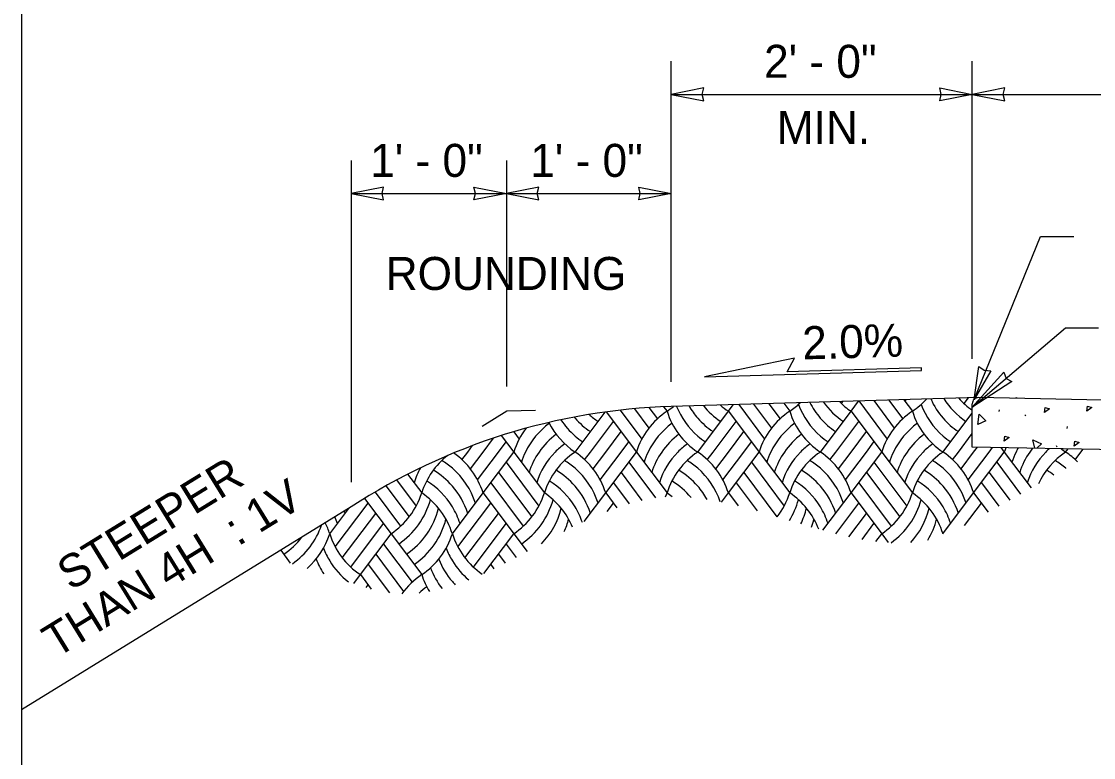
# Model space of a CAD drawing. Extents: x 99862 to 103151, y 100000 to 102076.
# Drawn here: x 99862 to 100381, y 101323 to 101680 of the extents above; entities that cross this region are included whole.
import ezdxf

# ---------------------------------------------------------------- set-up
doc = ezdxf.new("R2010")
doc.units = 0
for name, color, linetype in [('Level 1', 7, 'Continuous'), ('Level 13', 7, 'Continuous'), ('Level 15', 7, 'Continuous'), ('Level 20', 7, 'Continuous'), ('Level 28', 7, 'Continuous'), ('Level 34', 7, 'Continuous'), ('Level 4', 7, 'Continuous'), ('Level 6', 7, 'Continuous')]:
    doc.layers.add(name, color=color, linetype=linetype)

msp = doc.modelspace()

# ---------------------------------------------------------------- linework, layer by layer
at = {"layer": 'Level 1'}
msp.add_lwpolyline([(99862, 99999.5), (103151, 99999.5), (103151, 102075.5), (99862, 102075.5)], close=True, dxfattribs=at)
at = {"layer": 'Level 13'}
for p, q in [((100343.49, 101497.73), (100343.58, 101497.66)), ((100343.8, 101497.73), (100343.98, 101497.59)), ((100335.5, 101490.97), (100335.56, 101491.85)), ((100347.88, 101489.43), (100348.4, 101489.05)), ((100368.43, 101482.83), (100368.49, 101483.7)), ((100362.99, 101474.6), (100363.34, 101473.88))]:
    msp.add_line(p, q, dxfattribs=at)
for points in [[(100377.89, 101491.14), (100378.14, 101493.59), (100380.26, 101492.95), (100377.89, 101491.14)], [(100325.06, 101484.62), (100325.76, 101489.7), (100328.94, 101486.41), (100325.14, 101484.65)], [(100357.43, 101490.45), (100357.67, 101492.9), (100359.8, 101492.26), (100357.43, 101490.45)], [(100337.92, 101476.59), (100338.16, 101479.04), (100340.29, 101478.4), (100337.92, 101476.59)], [(100352.66, 101473.19), (100351.78, 101477.32), (100355.89, 101475.32), (100353.72, 101473.17)], [(100371.78, 101474.13), (100372.03, 101476.58), (100374.15, 101475.93), (100371.78, 101474.13)]]:
    msp.add_lwpolyline(points, dxfattribs=at)
at = {"layer": 'Level 15'}
for p, q in [((100176.64, 101516.59), (100176.64, 101660.67)), ((100322.4, 101516.59), (100322.4, 101660.67)), ((100176.64, 101644.67), (100322.4, 101644.67)), ((100322.4, 101644.67), (100753.65, 101644.67)), ((100021.66, 101612.67), (100021.66, 101456.76)), ((100096.8, 101612.67), (100096.8, 101503.09)), ((100021.66, 101596.67), (100096.8, 101596.67)), ((100096.8, 101596.67), (100176.64, 101596.67)), ((100176.64, 101505.43), (100176.64, 101596.67)), ((100323.3, 101496.87), (100355.53, 101575.76)), ((100355.53, 101575.76), (100371.53, 101575.76)), ((100322.2, 101492.93), (100367.51, 101531.52)), ((100367.51, 101531.52), (100383.51, 101531.52))]:
    msp.add_line(p, q, dxfattribs=at)
for points in [[(100176.64, 101644.67), (100192.37, 101641.59), (100191.64, 101644.67), (100192.37, 101647.76)], [(100322.4, 101644.67), (100306.68, 101641.59), (100307.4, 101644.67), (100306.68, 101647.76)], [(100322.4, 101644.67), (100338.13, 101641.59), (100337.4, 101644.67), (100338.13, 101647.76)], [(100021.66, 101596.67), (100037.39, 101593.59), (100036.66, 101596.67), (100037.39, 101599.76)], [(100096.8, 101596.67), (100081.07, 101593.59), (100081.8, 101596.67), (100081.07, 101599.76)], [(100096.8, 101596.67), (100112.52, 101593.59), (100111.8, 101596.67), (100112.52, 101599.76)], [(100176.64, 101596.67), (100160.92, 101593.59), (100161.64, 101596.67), (100160.92, 101599.76)], [(100322.2, 101492.93), (100337.64, 101510), (100338.77, 101507.04), (100341.51, 101505.46)], [(100323.3, 101496.87), (100325.52, 101512.74), (100328.2, 101511.05), (100331.35, 101510.73)]]:
    msp.add_lwpolyline(points, close=True, dxfattribs=at)
at = {"layer": 'Level 20'}
msp.add_lwpolyline([(100297.81, 101512.09), (100232.76, 101510.21), (100236.31, 101516.8), (100192.81, 101507.82), (100297.85, 101510.86)], close=True, dxfattribs=at)
at = {"layer": 'Level 28'}
for p, q in [((100325.46, 101497.73), (100176.64, 101493.43)), ((100097.02, 101491.13), (100085.1, 101483.8)), ((100111, 101491.53), (100097.02, 101491.13))]:
    msp.add_line(p, q, dxfattribs=at)
msp.add_arc((100185.68, 101193.57), 300, 91.7265, 123.1427, dxfattribs=at)
at = {"layer": 'Level 34'}
for p, q in [((100172.98, 101493.3), (100174.6, 101491.14)), ((100204.3, 101491.14), (100206.67, 101494.3)), ((100209.3, 101494.37), (100221.82, 101477.67)), ((100216.56, 101494.58), (100225.27, 101482.98)), ((100223.83, 101494.79), (100229.35, 101487.44)), ((100231.1, 101495), (100234, 101491.14)), ((100259.04, 101494.83), (100259.8, 101495.83)), ((100263.7, 101491.14), (100267.38, 101496.05)), ((100267.41, 101496.09), (100281.22, 101477.67)), ((100274.7, 101496.26), (100284.66, 101482.98)), ((100281.86, 101496.62), (100288.74, 101487.44)), ((100289.27, 101496.63), (100293.4, 101491.14)), ((100318.44, 101494.83), (100320.51, 101497.59)), ((100130.06, 101471.34), (100144.61, 101490.74)), ((100145.15, 101490.81), (100159.75, 101471.34)), ((100151.94, 101491.66), (100162.43, 101477.67)), ((100158.83, 101492.36), (100165.87, 101482.98)), ((100165.85, 101492.91), (100169.95, 101487.44)), ((100189.45, 101471.34), (100204.3, 101491.14)), ((100204.3, 101491.14), (100219.15, 101471.34)), ((100248.85, 101471.34), (100263.7, 101491.14)), ((100263.7, 101491.14), (100278.55, 101471.34)), ((100308.24, 101471.34), (100322.4, 101490.21)), ((100137.48, 101471.34), (100148.62, 101486.19)), ((100196.88, 101471.34), (100208.01, 101486.19)), ((100256.27, 101471.34), (100267.41, 101486.19)), ((100085.51, 101471.34), (100090.58, 101478.09)), ((100094.36, 101479.33), (100100.36, 101471.34)), ((100100.39, 101481.19), (100103.03, 101477.67)), ((100144.91, 101471.34), (100152.33, 101481.24)), ((100204.3, 101471.34), (100211.73, 101481.24)), ((100263.7, 101471.34), (100271.12, 101481.24)), ((100315.67, 101471.34), (100322.4, 101480.31)), ((100078.08, 101471.34), (100080.47, 101474.51)), ((100092.93, 101471.34), (100096.65, 101476.29)), ((100152.33, 101471.34), (100156.04, 101476.29)), ((100211.73, 101471.34), (100215.44, 101476.29)), ((100271.12, 101471.34), (100274.83, 101476.29)), ((100323.09, 101471.34), (100324.9, 101473.74)), ((100330.52, 101471.34), (100332.21, 101473.6)), ((100336.31, 101473.51), (100337.94, 101471.34)), ((100367.64, 101471.34), (100368.79, 101472.86)), ((100375.06, 101471.34), (100376.1, 101472.72)), ((100075.31, 101467.64), (100078.08, 101471.34)), ((100079.39, 101463.18), (100085.51, 101471.34)), ((100082.83, 101457.87), (100092.93, 101471.34)), ((100085.51, 101451.54), (100100.36, 101471.34)), ((100100.36, 101471.34), (100115.21, 101451.54)), ((100134.71, 101467.64), (100137.48, 101471.34)), ((100138.79, 101463.18), (100144.91, 101471.34)), ((100142.23, 101457.87), (100152.33, 101471.34)), ((100144.91, 101451.54), (100159.75, 101471.34)), ((100159.75, 101471.34), (100174.6, 101451.54)), ((100194.11, 101467.64), (100196.88, 101471.34)), ((100198.18, 101463.18), (100204.3, 101471.34)), ((100201.63, 101457.87), (100211.73, 101471.34)), ((100204.3, 101451.54), (100219.15, 101471.34)), ((100219.15, 101471.34), (100234, 101451.54)), ((100253.5, 101467.64), (100256.27, 101471.34)), ((100257.58, 101463.18), (100263.7, 101471.34)), ((100261.02, 101457.87), (100271.12, 101471.34)), ((100263.7, 101451.54), (100278.55, 101471.34)), ((100278.55, 101471.34), (100293.4, 101451.54)), ((100312.9, 101467.64), (100315.67, 101471.34)), ((100316.98, 101463.18), (100323.09, 101471.34)), ((100320.42, 101457.87), (100330.52, 101471.34)), ((100323.09, 101451.54), (100337.94, 101471.34)), ((100337.94, 101471.34), (100350.97, 101453.96)), ((100372.29, 101467.64), (100375.06, 101471.34)), ((100096.65, 101466.39), (100112.53, 101445.2)), ((100156.04, 101466.39), (100169.01, 101449.1)), ((100215.44, 101466.39), (100231.33, 101445.2)), ((100274.83, 101466.39), (100290.72, 101445.2)), ((100334.23, 101466.39), (100345.76, 101451.02)), ((100043.67, 101457.83), (100053.14, 101445.2)), ((100049, 101460.62), (100055.81, 101451.54)), ((100092.93, 101461.44), (100109.09, 101439.9)), ((100152.33, 101461.44), (100162.48, 101447.91)), ((100211.73, 101461.44), (100227.79, 101440.02)), ((100271.12, 101461.44), (100287.28, 101439.9)), ((100330.52, 101461.44), (100340.54, 101448.07)), ((100033.23, 101451.95), (100045.62, 101435.43)), ((100038.42, 101454.93), (100049.69, 101439.9)), ((100070.66, 101431.74), (100085.51, 101451.54)), ((100085.51, 101451.54), (100100.36, 101431.74)), ((100089.22, 101456.49), (100105.01, 101435.43)), ((100134.48, 101437.64), (100144.91, 101451.54)), ((100144.91, 101451.54), (100150.28, 101444.37)), ((100148.62, 101456.49), (100156.24, 101446.33)), ((100201, 101447.13), (100204.3, 101451.54)), ((100204.3, 101451.54), (100208.99, 101445.29)), ((100208.01, 101456.49), (100218.28, 101442.8)), ((100250.11, 101433.43), (100263.7, 101451.54)), ((100263.7, 101451.54), (100278.55, 101431.74)), ((100267.41, 101456.49), (100283.2, 101435.43)), ((100308.24, 101431.74), (100323.09, 101451.54)), ((100323.09, 101451.54), (100330.11, 101442.19)), ((100326.81, 101456.49), (100335.32, 101445.13)), ((100013.94, 101425.4), (100029.83, 101446.59)), ((100028.12, 101448.86), (100040.96, 101431.74)), ((100073.33, 101425.4), (100089.22, 101446.59)), ((100145.59, 101442.55), (100148.62, 101446.59)), ((100256.32, 101431.8), (100267.41, 101446.59)), ((100318.66, 101435.73), (100326.81, 101446.59)), ((100011.26, 101431.74), (100020.49, 101444.04)), ((100017.38, 101420.1), (100033.54, 101441.64)), ((100076.78, 101420.1), (100092.93, 101441.64)), ((100262.63, 101430.32), (100271.12, 101441.64)), ((100021.46, 101415.63), (100037.25, 101436.69)), ((100080.86, 101415.63), (100096.65, 101436.69)), ((100269.09, 101429.03), (100274.83, 101436.69)), ((100026.11, 101411.94), (100040.96, 101431.74)), ((100040.96, 101431.74), (100055.81, 101411.94)), ((100085.97, 101412.56), (100100.36, 101431.74)), ((100100.36, 101431.74), (100106.83, 101423.11)), ((100275.77, 101428.04), (100278.55, 101431.74)), ((100278.55, 101431.74), (100281.71, 101427.52)), ((100037.25, 101426.79), (100051.16, 101408.25)), ((100096.65, 101426.79), (100101.52, 101420.29)), ((99987.55, 101423.77), (99992.18, 101417.58)), ((100033.54, 101421.84), (100047.08, 101403.78)), ((100092.93, 101421.84), (100096.18, 101417.51)), ((100029.83, 101416.89), (100040.2, 101403.06)), ((100089.22, 101416.89), (100090.77, 101414.83)), ((100022.91, 101407.67), (100026.11, 101411.94)), ((100026.11, 101411.94), (100031.36, 101404.94)), ((100028.89, 101405.74), (100029.83, 101406.99))]:
    msp.add_line(p, q, dxfattribs=at)
for centre, start, end in [((100153.64, 101522.32), 303.9036, 309.8156), ((100214.13, 101507.47), 201.8244, 228.9599), ((100217.84, 101512.42), 209.9238, 220.9416), ((100221.55, 101517.37), 218.6985, 236.0964), ((100225.26, 101522.32), 228.6448, 236.0964), ((100213.04, 101522.32), 303.9036, 313.8709), ((100273.52, 101507.47), 200.2432, 228.9599), ((100277.23, 101512.42), 206.9922, 220.9416), ((100280.95, 101517.37), 215.4869, 236.0964), ((100284.66, 101522.32), 224.9354, 236.0964), ((100268.72, 101527.27), 303.9036, 305.3853), ((100272.44, 101522.32), 303.9036, 317.6315), ((100332.92, 101507.47), 200.2432, 228.9599), ((100336.63, 101512.42), 204.1301, 220.9416), ((100340.34, 101517.37), 212.3917, 236.0964), ((100344.05, 101522.32), 221.4398, 234.814), ((100158.44, 101512.42), 219.9686, 220.9416), ((100162.15, 101517.37), 227.7254, 236.0964), ((100195.56, 101459.95), 123.9036, 162.3566), ((100210.41, 101502.52), 197.6434, 236.0964), ((100254.96, 101459.95), 123.9036, 162.3566), ((100269.81, 101502.52), 197.6434, 236.0964), ((100314.36, 101459.95), 123.9036, 162.3566), ((100329.21, 101502.52), 197.6434, 236.0964), ((100136.17, 101459.95), 142.3389, 162.3566), ((100139.88, 101455), 126.3063, 154.2266), ((100151.02, 101502.52), 206.6043, 236.0964), ((100154.73, 101507.47), 213.0285, 228.9599), ((100158.44, 101512.42), 220.9415, 236.0964), ((100199.28, 101455), 126.3063, 154.2266), ((100217.84, 101512.42), 220.9415, 236.0964), ((100258.67, 101455), 126.3063, 154.2266), ((100277.23, 101512.42), 220.9415, 236.0964), ((100318.07, 101455), 126.3063, 154.2266), ((100336.63, 101512.42), 220.9415, 236.0964), ((100143.59, 101450.05), 127.1006, 145.4911), ((100154.73, 101507.47), 228.9599, 236.0964), ((100202.99, 101450.05), 127.1006, 145.4911), ((100214.12, 101507.47), 228.9599, 236.0964), ((100262.38, 101450.05), 127.1006, 145.4911), ((100273.52, 101507.47), 228.9599, 236.0964), ((100321.78, 101450.05), 127.1006, 145.4911), ((100332.92, 101507.47), 228.9599, 236.0964), ((100147.31, 101445.1), 126.331, 135.7128), ((100206.7, 101445.1), 126.331, 135.7128), ((100266.1, 101445.1), 126.331, 135.7128), ((100325.49, 101445.1), 126.331, 135.7128), ((100373.75, 101459.95), 158.9143, 162.3566), ((100377.46, 101455), 150.7709, 154.2266), ((100381.18, 101450.05), 141.9503, 145.4911), ((100384.89, 101445.1), 131.9516, 135.7128), ((100388.6, 101502.52), 231.9565, 236.0964), ((100091.62, 101440.15), 128.1669, 162.3566), ((100045.99, 101435.2), 48.9597, 58.5465), ((100049.7, 101440.15), 17.6434, 54.9273), ((100139.88, 101455), 154.2265, 162.3566), ((100143.59, 101450.05), 145.491, 162.3566), ((100147.31, 101445.1), 135.7127, 162.3566), ((100151.02, 101440.15), 123.9036, 162.3566), ((100105.38, 101435.2), 48.9597, 58.5465), ((100109.1, 101440.15), 17.6434, 56.0963), ((100199.28, 101455), 154.2265, 162.3566), ((100202.99, 101450.05), 145.491, 162.3566), ((100206.7, 101445.1), 135.7127, 162.3566), ((100210.41, 101440.15), 123.9036, 162.3566), ((100164.78, 101435.2), 48.9597, 58.5465), ((100168.49, 101440.15), 17.6434, 56.0963), ((100258.67, 101455), 154.2265, 162.3566), ((100262.38, 101450.05), 145.491, 162.3566), ((100266.1, 101445.1), 135.7127, 162.3566), ((100269.81, 101440.15), 123.9036, 162.3566), ((100224.18, 101435.2), 48.9597, 58.5465), ((100227.89, 101440.15), 17.6434, 56.0963), ((100318.07, 101455), 154.2265, 162.3566), ((100321.78, 101450.05), 145.491, 162.3566), ((100325.49, 101445.1), 135.7127, 162.3566), ((100329.21, 101440.15), 123.9036, 162.3566), ((100283.57, 101435.2), 48.9597, 58.5465), ((100287.28, 101440.15), 17.6434, 56.0963), ((100377.46, 101455), 154.2265, 162.3566), ((100381.18, 101450.05), 145.491, 162.3566), ((100384.89, 101445.1), 135.7127, 162.3566), ((100388.6, 101440.15), 123.9036, 155.1174), ((100342.97, 101435.2), 48.9597, 58.5465), ((100346.68, 101440.15), 44.7448, 56.0963), ((100087.91, 101445.1), 150.2466, 162.3566), ((100042.28, 101430.25), 40.9413, 59.3021), ((100045.99, 101435.2), 17.6434, 48.9597), ((100101.67, 101430.25), 40.9413, 59.3021), ((100105.38, 101435.2), 17.6434, 48.9597), ((100161.07, 101430.25), 40.9413, 59.3021), ((100164.78, 101435.2), 18.7051, 48.9597), ((100220.46, 101430.25), 40.9413, 59.3021), ((100224.18, 101435.2), 17.6434, 48.9597), ((100279.86, 101430.25), 40.9413, 59.3021), ((100283.57, 101435.2), 17.6434, 48.9597), ((100339.26, 101430.25), 52.7864, 59.3021), ((100342.97, 101435.2), 48.7157, 48.9597), ((100038.56, 101425.3), 31.3316, 58.4874), ((100097.96, 101425.3), 31.3316, 58.4874), ((100157.36, 101425.3), 39.8281, 58.4874), ((100216.75, 101425.3), 31.3316, 58.4874), ((100276.15, 101425.3), 31.3316, 58.4874), ((100020, 101462.93), 303.9036, 342.3566), ((100034.85, 101420.35), 17.6434, 56.0964), ((100042.27, 101430.25), 17.6434, 40.9414), ((100079.4, 101462.93), 303.9036, 342.3566), ((100094.25, 101420.35), 22.7508, 56.0964), ((100101.67, 101430.25), 17.6434, 40.9414), ((100138.79, 101462.93), 339.2243, 342.3566), ((100153.64, 101420.35), 51.3868, 56.0964), ((100161.07, 101430.25), 28.9037, 40.9414), ((100198.19, 101462.93), 322.35, 342.3566), ((100213.04, 101420.35), 21.3055, 56.0964), ((100220.46, 101430.25), 17.6434, 40.9414), ((100257.59, 101462.93), 303.9036, 342.3566), ((100272.44, 101420.35), 17.6434, 56.0964), ((100279.86, 101430.25), 17.6434, 40.9414), ((100023.71, 101457.98), 303.9036, 345.0113), ((100083.11, 101457.98), 303.9036, 345.0113), ((100201.9, 101457.98), 328.2267, 345.0113), ((100261.3, 101457.98), 305.6428, 345.0113), ((99982.88, 101430.25), 17.6434, 19.3659), ((100027.43, 101453.03), 303.9036, 346.3199), ((100038.56, 101425.3), 17.6434, 31.3317), ((100086.82, 101453.03), 315.9567, 346.3199), ((100097.96, 101425.3), 18.4944, 31.3317), ((100205.61, 101453.03), 333.9524, 346.3199), ((100216.75, 101425.3), 17.6434, 31.3317), ((100265.01, 101453.03), 317.315, 346.3199), ((100276.15, 101425.3), 17.6434, 31.3317), ((99971.74, 101448.08), 304.8705, 341.126), ((99975.46, 101420.35), 17.6434, 26.3747), ((99979.17, 101425.3), 17.6434, 22.8864), ((100031.14, 101448.08), 303.9036, 345.7713), ((100090.53, 101448.08), 336.0248, 345.7713), ((100209.33, 101448.08), 339.6426, 345.7713), ((100268.72, 101448.08), 328.9873, 345.7713), ((99975.46, 101443.13), 311.4379, 342.3566), ((100047.07, 101443.13), 197.6435, 236.0964), ((100034.85, 101443.13), 303.9036, 342.3566), ((100106.47, 101443.13), 197.6435, 235.4015), ((99968.03, 101453.03), 303.9036, 322.3196), ((100043.36, 101438.18), 200.8778, 211.332), ((100102.76, 101438.18), 200.8778, 211.332), ((100039.65, 101433.23), 201.4344, 213.7551), ((100043.36, 101438.18), 211.3319, 232.1349), ((100095.33, 101428.28), 200.2432, 217.9679), ((100099.05, 101433.23), 201.4344, 220.9416), ((100102.76, 101438.18), 211.3319, 229.946), ((100076.77, 101380.75), 123.9036, 144.4336), ((100091.62, 101423.33), 197.6434, 211.4478), ((100080.48, 101375.8), 126.3063, 133.6306), ((100099.05, 101433.23), 220.9415, 224.1663)]:
    msp.add_arc(centre, 37.58, start, end, dxfattribs=at)
at = {"layer": 'Level 4'}
msp.add_line((100021.66, 101444.76), (99862, 101346.51), dxfattribs=at)
at = {"layer": 'Level 6'}
for p, q in [((100322.4, 101473.79), (100322.4, 101494.73)), ((100749.21, 101489.26), (100325.46, 101497.73)), ((100752.15, 101465.2), (100322.4, 101473.79))]:
    msp.add_line(p, q, dxfattribs=at)
msp.add_arc((100325.4, 101494.73), 3, 88.8542, 180, dxfattribs=at)

# ---------------------------------------------------------------- texts
at = {"layer": 'Level 20'}
for s, p in [('2\' - 0"', (100221.61, 101652.67)), ('MIN.', (100227.77, 101620.67)), ('1\' - 0"', (100030.89, 101604.67)), ('1\' - 0"', (100108.38, 101604.67)), ('ROUNDING', (100038.4, 101549.88))]:
    msp.add_text(s, height=16, dxfattribs=at).set_placement(p)
for s, rotation, p in [('2.0%', 1.6555, (100240.34, 101516.21)), ('STEEPER', 31.606, (99885.89, 101403.84)), ('THAN 4H  : 1V', 31.606, (99878.79, 101371.29))]:
    msp.add_text(s, height=16, rotation=rotation, dxfattribs=at).set_placement(p)

doc.saveas('drawing.dxf')
